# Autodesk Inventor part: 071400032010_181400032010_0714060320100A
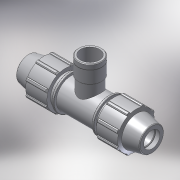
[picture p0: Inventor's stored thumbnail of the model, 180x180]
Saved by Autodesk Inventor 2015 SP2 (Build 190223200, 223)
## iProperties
Created: 2017-02
Part Number: 071400032010_181400032010_0714060320100A
Material: PVC-Piping
Description: PLASSON TEE WITH THREADED FEMALE OFFTAKE 32-1"-32
Document SubType Name: Modeling
Designer: KIM
Mass: 92.6774 g
Surface Area: 199.44 cm^2
Volume: 66.1981 cm^3
Density: 1.4 g/cm^3
Appearance: Smooth - White
Author: KIM
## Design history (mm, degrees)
derived "07140.ipt"
feature "Solid1::07140.ipt"
feature "Solid2::07140.ipt"
tag "TaggingFeature1"
body "Solid1"
other parameters: "d2" = 32, "d4" = 7.375, "d5" = 21.24, "d7" = 64, "d11" = 2.95, "d13" = 120 deg, "d14" = 48, "d15" = 12 deg, "d16" = 55.68, "d18" = 1.6, "d19" = 35 deg, "d20" = 17.5 deg, "d21" = 59.52, "d23" = 0, "d25" = 360 deg, "d27" = 1.28, "d33" = 0.64, "d42" = 31.86, "d43" = 1.92, "d46" = 0.96, "d68" = 5.31, "d72" = 54, "d76" = 30.291, "d80" = 0.90873, "d91" = 48, "d93" = 67, "d95" = 28.8, "d112" = 21, "d115" = 37.86375, "d116" = 135 deg, "d117" = 34.83465, "d118" = 177, "d119" = 28.8, "d121" = 0, "d122" = 28.8, "d124" = 0, "d128" = 0, "d129" = 3.2, "d130" = 6.3, "d131" = 0.3, "d132" = 0.3, "d133" = 37.86375, "d_" = 32, "E_" = 64, "A_" = 54, "l_" = 67, "l_2" = 21, "Rp_" = 30.291, "H_" = 177
